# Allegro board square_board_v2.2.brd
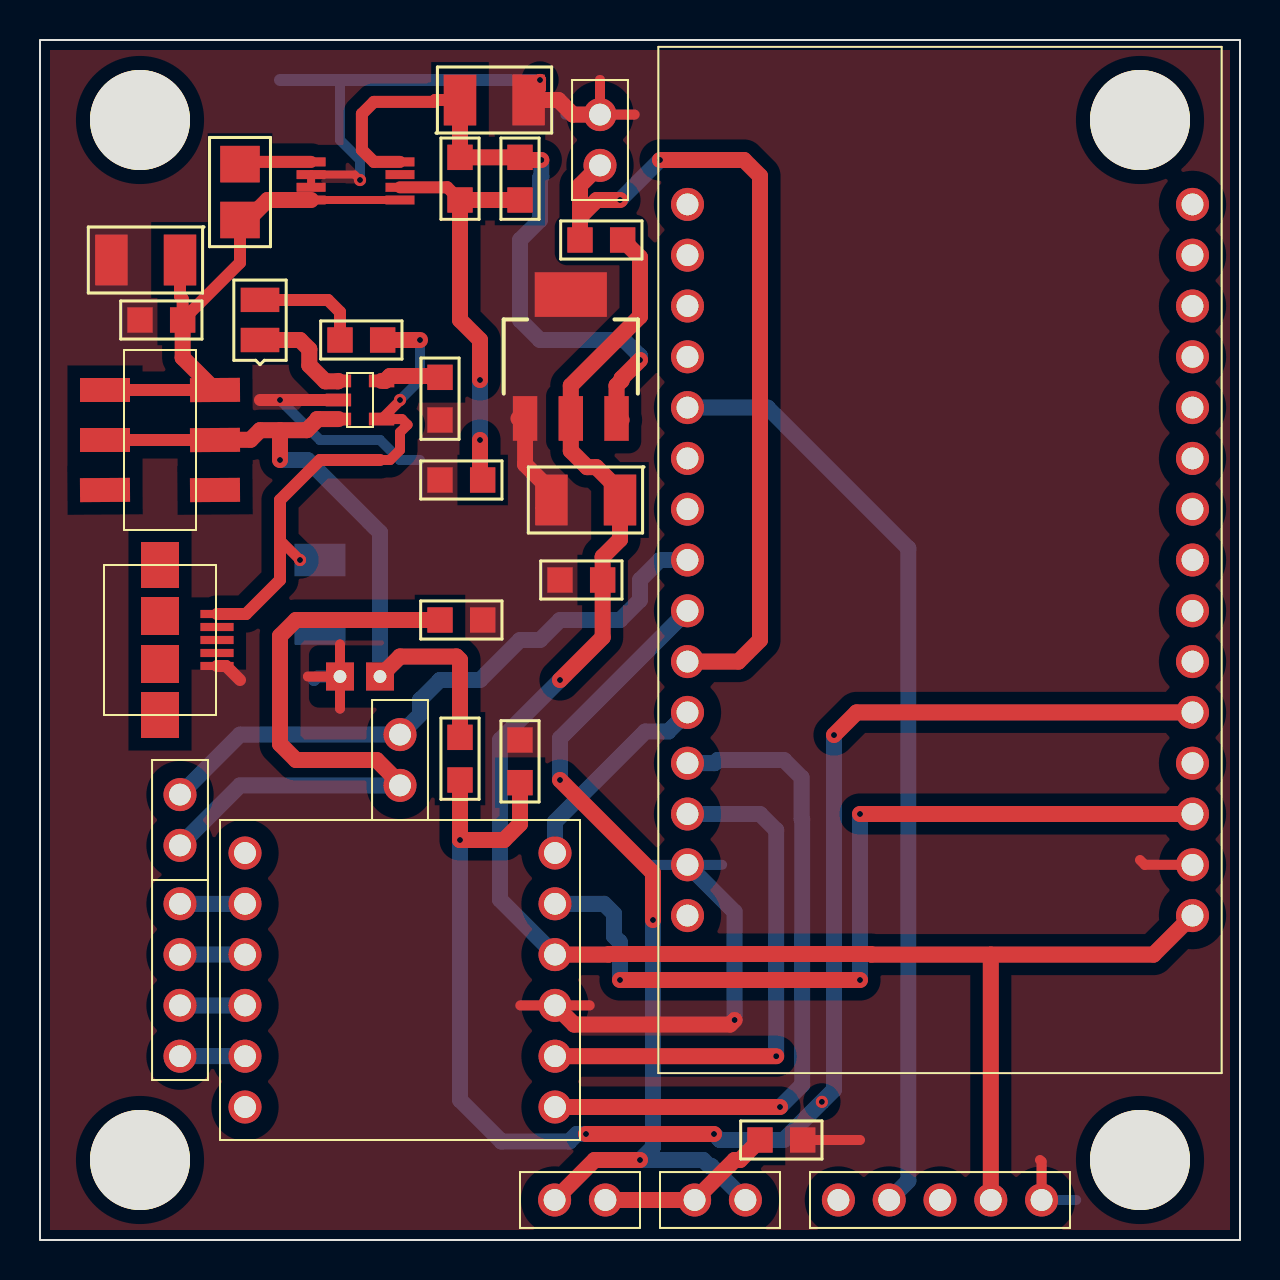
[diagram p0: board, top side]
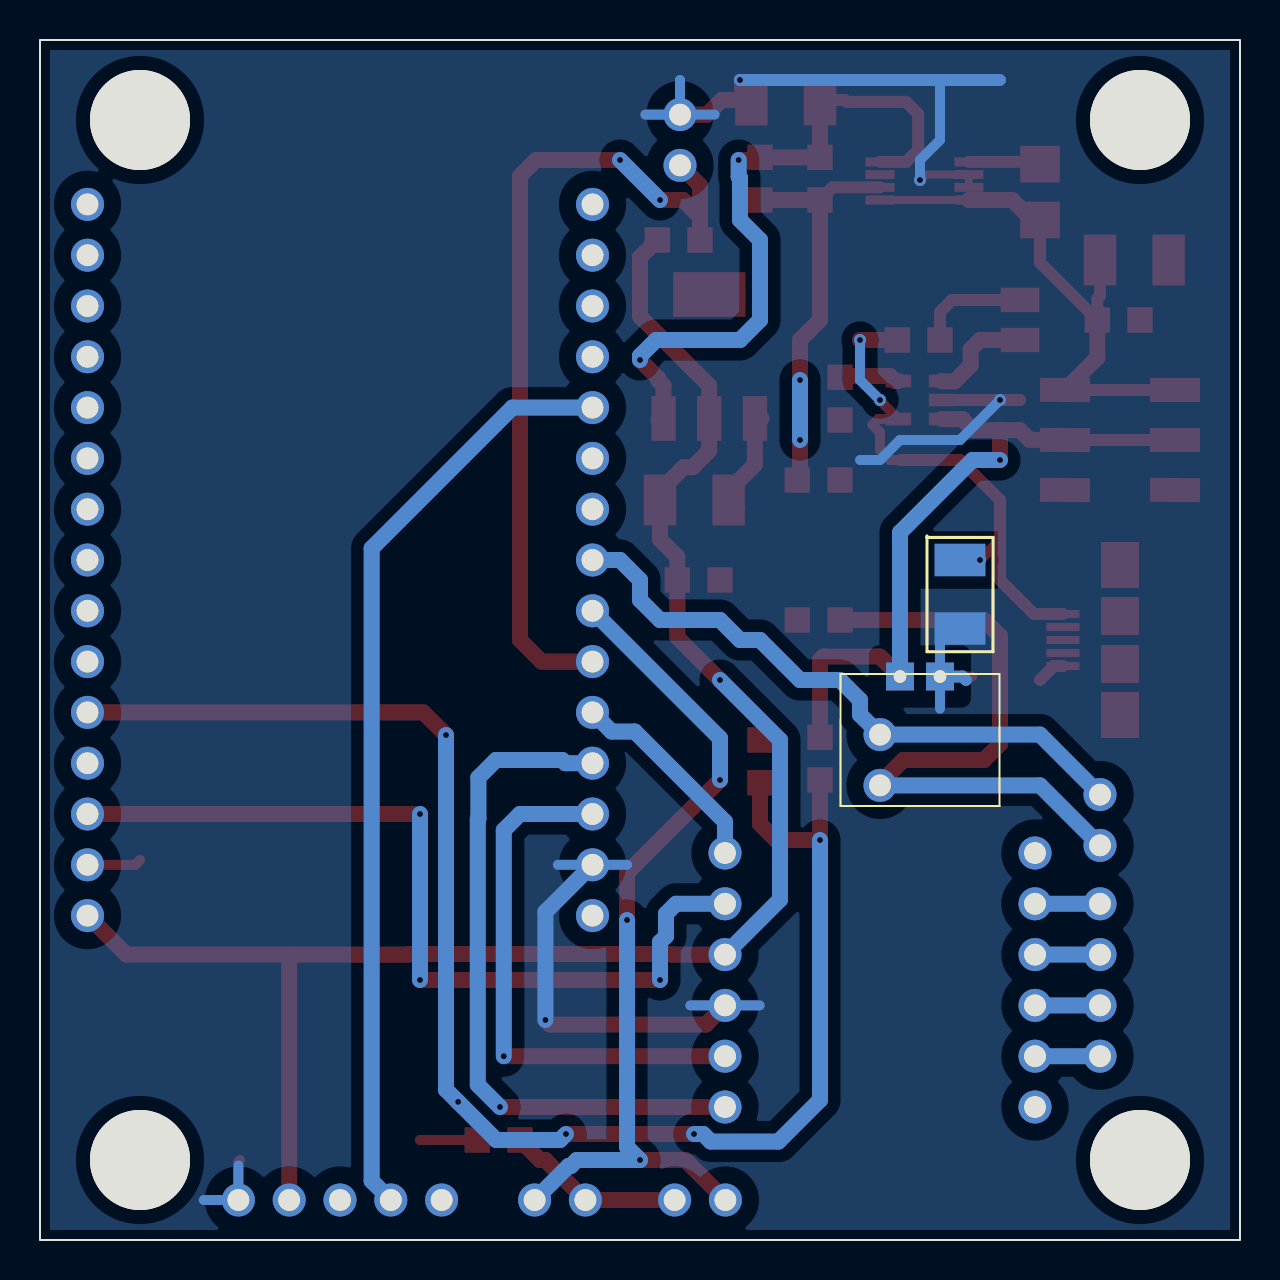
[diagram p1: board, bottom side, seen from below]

Outline 60 x 60 mm; copper layers: TOP, BOTTOM. Coordinates in mm from the lower left corner of the outline.
Outline path: rectangle 0,0 60,60

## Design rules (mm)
constraint set DEFAULT: min track width 0.5

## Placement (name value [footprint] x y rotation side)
C1  10u  [SMCT1210]  14 34 270 bottom
C2  120n  [SMC0805]  5 46 0 top
C3  10u  [SMCT1210]  7 49 180 top
C4  27p  [SMC0805]  24 52 90 top
C5  10u  [SMCT1210]  21 57 0 top
C6  120n  [SMC0805]  26 33 0 top
C7  10u  [SMCT1210]  29 37 180 top
D1  LED_RED  [SMD0805]  11 45 90 top
J1  Batterie_Lithium  [CONALIM]  16 25 0 bottom
J2  Photoresistance  [CONN2_FOOT]  28 55 0 top
J3  Micro  [CONN5_FOOT]  45 2 270 top
J4  Diode blanche1  [CONN2_FOOT]  7 21 0 top
J5  Diode rouge1  [CONN2_FOOT]  34 2 270 top
J6  Diode blanche2  [CONN2_FOOT]  18 24 0 top
J7  connDRV  [DRV_FOOT]  18 13 180 top
J8  Motors  [CONN4_FOOT]  7 13 180 top
J9  Diode rouge2  [CONN2_FOOT]  27 2 90 top
L1  4.7uH  [SML1210]  10 51 90 top
NOREF  -  [unnamed]  5 4 0 top
NOREF#2  -  [unnamed]  5 56 0 top
NOREF#3  -  [unnamed]  55 4 0 top
NOREF#4  -  [unnamed]  55 56 0 top
R1  2k  [SMR0805]  20 41 90 top
R2  470  [SMR0805]  15 45 0 top
R3  976k  [SMR0805]  21 52 90 top
R4  309k  [SMR0805]  20 38 0 top
R5  2k  [SMR0805]  21 23 90 top
R6  2k  [SMR0805]  24 25 270 top
R7  2k  [SMR0805]  27 50 0 top
R8  2k  [SMR0805]  20 31 0 top
R9  2k  [SMR0805]  36 5 0 top
SW1  Interrupteur  [INTERUPTEUR]  6 40 0 top
U1  MCP73831  [5LEADSOT23]  16 42 0 top
U2  MCP1642  [MSOP8]  18 52 90 top
U3  LD1117S33TR  [TO261AASOT223]  24 41 0 top
U4  connUSB  [CONUSB]  6 30 270 top
U5  esp32  [ESP_32]  45 34 0 top

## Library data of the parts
C1 C3 C5 C7 = CP
C2 C4 C6 = C
D1 = LED0805
J1 = CON2_0
J2 = conn2
J3 = conn5_0
J4-J6 J9 = conn2_1
J7 = connDRV
J8 = conn4
L1 = L
R1-R9 = R
SW1 = SW KEY-Y1011_0
U1 = MCP73831
U2 = MCP1642_1
U3 = LD1117S33TR_0
U4 = connUSB_1
U5 = esp32

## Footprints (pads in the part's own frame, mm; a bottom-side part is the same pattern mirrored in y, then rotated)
5LEADSOT23
  rect 1.27x0.635 smd: 1(-1.079,0.953) 2(-1.079,0) 3(-1.079,-0.953) 4(1.079,-0.953) 5(1.079,0.953)
CONALIM
  rect 1.397x1.397 hole 0.635: +(1,-3.175) -(-1,-3.175)
CONN2_FOOT
  round 1.651 hole 1.092: 1(0,1.27) 2(0,-1.27)
CONN4_FOOT
  round 1.651 hole 1.092: 1(0,3.81) 2(0,1.27) 3(0,-1.27) 4(0,-3.81)
CONN5_FOOT
  round 1.651 hole 1.092: 1(0,5.08) 2(0,2.54) 3(0,0) 4(0,-2.54) 5(0,-5.08)
CONUSB
  rect 0.406x1.651 smd: 1(-1.3,2.85) 2(-0.65,2.85) 3(0,2.85) 4(0.65,2.85) 5(1.3,2.85)
  rect 1.9x1.9 smd: 6(-1.2,0) 7(1.2,0)
  rect 2.3x1.9 smd: 8(-3.75,0) 9(3.75,0)
DRV_FOOT
  round 1.651 hole 1.092: 1(-7.75,6.35) 2(-7.75,3.81) 3(-7.75,1.27) 4(-7.75,-1.27) 5(-7.75,-3.81) 6(-7.75,-6.35) 7(7.75,-6.35) 8(7.75,-3.81) 9(7.75,-1.27) 10(7.75,1.27) 11(7.75,3.81) 12(7.75,6.35)
ESP_32
  round 1.651 hole 1.092: 1(-12.625,17.78) 2(-12.625,15.24) 3(-12.625,12.7) 4(-12.625,10.16) 5(-12.625,7.62) 6(-12.625,5.08) 7(-12.625,2.54) 8(-12.625,0) 9(-12.625,-2.54) 10(-12.625,-5.08) 11(-12.625,-7.62) 12(-12.625,-10.16) 13(-12.625,-12.7) 14(-12.625,-15.24) 15(-12.625,-17.78) 16(12.625,-17.78) 17(12.625,-15.24) 18(12.625,-12.7) 19(12.625,-10.16) 20(12.625,-7.62) 21(12.625,-5.08) 22(12.625,-2.54) 23(12.625,0) 24(12.625,2.54) 25(12.625,5.08) 26(12.625,7.62) 27(12.625,10.16) 28(12.625,12.7) 29(12.625,15.24) 30(12.625,17.78)
INTERUPTEUR
  rect 2.5x1.2 smd: 1(-2.75,2.5) 2(-2.75,0)
  rect 1.2x2.5 smd rot 90.4: 3(-2.75,-2.5) 4(2.75,2.5) 5(2.75,0) 6(2.75,-2.5)
MSOP8
  rect 0.45x1.45 smd: 1(0,0) 2(0.635,0) 3(1.27,0) 4(1.905,0) 5(1.905,4.445) 6(1.27,4.445) 7(0.635,4.445) 8(0,4.445)
SMC0805
  rect 1.27x1.27 smd: 1(0,0) 2(2.134,0)
SMCT1210
  rect 1.626x2.54 smd: 1(0,0) 2(3.429,0)
SMD0805
  rect 1.219x1.93 smd: A(2.007,0) C(0,0)
SML1210
  rect 1.829x1.981 smd: 1(0,0) 2(2.794,0)
SMR0805
  rect 1.27x1.27 smd: 1(0,0) 2(2.134,0)
TO261AASOT223
  rect 1.219x2.235 smd: 1(0,0) 2(2.54,0) 3(5.08,0)
  rect 3.607x2.235 smd: 4(2.54,6.35)
unnamed
  round 5 hole 5 unplated: (0,0)

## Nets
3.3V: C6.2 C7.1 J3.2(VDD) J7.4 R7.2 U3.2(VOUT) U5.16
5V: C4.2 C5.1 R3.2 U2.4(VOUT) U3.3
VIN: U5.15
0: C1.2 C2.1 C3.2 C5.2 C6.1 C7.2 J1.- J2.1 J3.1 J7.3 R1.1 R4.1 R6.1 R8.2 R9.2 U1.2(VSS) U2.6 U2.7 U3.1 U3.4 U4.5 U5.14 U5.17
VUSB: C1.1 R2.2 U1.4 U4.1(VCC)
N70085: J1.+ R5.2 SW1.2 SW1.5 U1.3
N70105: R1.2 U1.5
N70321: C2.2 C3.1 L1.1 SW1.1 SW1.4 U2.1 U2.8
N74007: L1.2 U2.5
N74339: C4.1 R3.1 R4.2 U2.2
N76144: J3.4 U5.5
N76694: J7.11 J8.1
N76698: J7.10 J8.2
N76711: J7.8 J8.4(OUT4)
N76717: J7.9 J8.3
N77907: J7.1 U5.12
N79860: J5.2(-) J9.2(-) R9.1
N80233: J4.2(-) J6.2(-) R8.1
N80351: J4.1 J6.1 U5.8
N80525: J5.1 J9.1 U5.9
N80737: J2.2(OUT2) R7.1 U5.10
N87816: J7.2 U5.13
N87824: J7.6 U5.11
N94189: R5.1 R6.2 U5.20
N98470: J7.5 U5.18
N700530: D1.C(CATHODE) U1.1
N701570: D1.A R2.1

Pads without a net: J3 3 5; J7 7 12; SW1 3 6; U2 3; U4 2 3 4 6 7 8 9; U5 1 2 3 4 6 7 19 21 22 23 24 25 26 27 28 29 30

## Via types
v1: diameter 0.61, hole 0.3, TOP to BOTTOM, 28 vias

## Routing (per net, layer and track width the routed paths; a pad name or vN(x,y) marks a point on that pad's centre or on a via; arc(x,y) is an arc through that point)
3.3V: length 87.4
  TOP w0.8: U5.16 55.67,14.27 47.54,14.27 ; R7.2 30,49.13 30,46.18 26.54,42.72 U3.2 26.54,39.46 27.36,38.64 27.81,38.64 29,37.46 C7.1 29,35.03 28.13,34.16 C6.2 28.13,30.13 v1(26,28) ; J3.2 47.54,14.27 ; 47.54,14.27 41.57,14.27 41.54,14.3 28.46,14.3 28.43,14.27 J7.4
  BOTTOM w0.8: v1(26,28) 23,25 23,17.02 J7.4
5V: length 35.1
  TOP w0.6: C5.1 19.76,57 19.67,56.91 16.7,56.91 16.09,56.3 16.09,54.5 16.7,53.91 U2.4
  TOP w0.8: v1(30,44) 29.08,43.08 29.08,42.97 28.83,42.72 28.83,41.25 U3.3 ; v1(25.07,54) 24.13,54 C4.2 R3.2 C5.1
  BOTTOM w0.8: v1(25.07,54) 25.07,53.17 25,53.1 25,51 24,50 24,46 25,45 29.2,45 30,44.2 v1(30,44)
0: length 104
  TOP w0.4: v1(16,53) 15.73,53.27 U2.6 U2.7
  TOP w0.5: R9.2 41,5 ; 50,4 50.08,3.92 J3.1 ; 13.39,28.18 15,28.18 ; 15,28.18 15,26.57 ; 15,28.18 15,29.78 ; 28,58 J2.1 29.73,56.27 ; 24.02,11.73 J7.3 27.48,11.73 ; U5.17 55.24,18.76 55,19
  TOP w0.6: 11,42 v1(12,42) U1.2 ; 10,28 9.3,28.7 U4.5 ; 24.25,40.75 U3.1 ; C5.2 25,57.57 v1(25,58) ; 19.73,41 R1.1 ; C7.2 25.57,37.46
  TOP w0.8: J7.3 26.71,10.77 34.5,10.77 v1(34.73,11) ; 25.16,36.59 C7.2 ; 24.25,40.75 24.25,38.77 25.57,37.46 ; J2.1 26.65,56.27 25.92,57 C5.2 ; 24.25,41.25 U3.1 23.92,41.08
  BOTTOM w0.5: 15,29.78 15,26.57 ; J2.1 28,58 ; J2.1 26.27,56.27 ; J2.1 29.73,56.27 ; 30.64,18.76 U5.14 34.11,18.76 ; 27.48,11.73 J7.3 24.02,11.73 ; v1(12,42) 14,40 17,40 18,39 19,39 ; 51.81,2 J3.1 50.08,3.73 ; v1(16,53) 16,54 15,55 15,58
  BOTTOM w0.6: v1(25,58) 12,58 ; 15,28.18 13.87,28.18 13.7,28
  BOTTOM w0.8: U5.14 34.73,16.41 v1(34.73,11)
VUSB: length 26.8
  TOP w0.5: v1(13,34) 12,35 ; 17,39 17.5,39 18,39.5 18,40.38 18.38,40.76 18.09,41.05 U1.4 18,41.97 v1(18,42)
  TOP w0.6: U4.1 10.3,31.3 12,33 12,37 14,39 17,39
  TOP w0.8: R2.2 v1(19,45)
  BOTTOM w0.5: v1(18,42) 19,43 v1(19,45) ; C1.1 v1(13,34)
N70085: length 35.7
  TOP w0.6: SW1.2 SW1.5
  TOP w0.8: 12,40.49 v1(12,39) ; 12,40.49 13.34,40.49 13.87,41.02 13.87,41.05 U1.3 ; 12,40.49 11,40.49 10.53,40.01 SW1.5 ; 17,28.18 18,29.18 20.82,29.18 21,29 R5.2
  BOTTOM w0.8: v1(12,39) 13.37,39 17,35.37 17,28.18
N70105: length 3.1
  TOP w0.8: U1.5 17.26,42.95 17.5,43.2 19.5,43.2 19.56,43.13 R1.2
N70321: length 27.5
  TOP w0.4: U2.8 U2.1
  TOP w0.6: SW1.1 SW1.4 ; L1.1 10,48.87 C2.2 7.13,47.06 7,47.2 C3.1
  TOP w0.8: SW1.4 7.13,44.12 C2.2 7,46.13 ; U2.8 11.38,52 10.38,51 L1.1
N74007: length 3.6
  TOP w0.6: L1.2 10.11,53.91 U2.5
N74339: length 20.7
  TOP w0.6: U2.2 20.37,52.64 R3.1
  TOP w0.8: v1(22,40) 22,38.13 R4.2 ; v1(22,43) 22,45 21,46 R3.1 C4.1
  BOTTOM w0.8: v1(22,43) v1(22,40)
N76144: length 46.9
  BOTTOM w0.8: U5.5 36.38,41.62 43.42,34.58 43.42,2.96 J3.4
N76694: length 3.2
  BOTTOM w0.8: J8.1 J7.11
N76698: length 3.2
  BOTTOM w0.8: J8.2 J7.10
N76711: length 3.2
  BOTTOM w0.8: J8.4 J7.8
N76717: length 3.2
  BOTTOM w0.8: J8.3 J7.9
N77907: length 34.3
  TOP w0.8: v1(37,6.65) J7.1
  BOTTOM w0.8: U5.12 33.73,23.84 33.89,24 37.2,24 38.08,23.12 38.08,21.06 38.11,21.03 38.11,7.76 v1(37,6.65)
N79860: length 9
  TOP w0.8: R9.1 35,4 34.73,4 J5.2 J9.2
N80233: length 32.9
  TOP w0.8: R8.1 12.8,31 12,30.2 12,24.8 12.8,24 16.83,24 18,22.83 J6.2
  BOTTOM w0.8: J4.2 10,22.73 J6.2
N80351: length 31.2
  BOTTOM w0.8: U5.8 31,34 30,33 30,32 29,31 26,31 25,30 24,30 22,28 20,28 19,27 19,26.27 J6.1 10,25.27 J4.1
N80525: length 43.5
  TOP w0.8: v1(30,4) 27.73,4 J9.1 ; v1(30.65,16) 30.65,18.35 v1(26,23)
  BOTTOM w0.8: J5.1 33.57,3.7 33.46,3.7 33.16,4 v1(30,4) 30.65,4.65 v1(30.65,16) ; U5.9 26,25.09 v1(26,23)
N80737: length 41.9
  TOP w0.8: 27,51.16 27.84,52 v1(29,52) ; 27,51.16 R7.1 ; 27,51.16 27,52.73 J2.2 ; U5.10 34.92,28.92 36,30 36,53.2 35.2,54 v1(31,54)
  BOTTOM w0.8: v1(31,54) v1(29,52)
N87816: length 27.1
  TOP w0.8: J7.2 v1(36.81,9.19)
  BOTTOM w0.8: U5.13 36,21.3 36.81,20.49 v1(36.81,9.19)
N87824: length 10.5
  BOTTOM w0.8: U5.11 31.42,25.42 30.26,25.42 25.75,20.91 J7.6
N94189: length 78.4
  TOP w0.8: U5.20 40.83,26.38 v1(39.7,25.25) ; R5.1 v1(21,20) 23.2,20 24,20.8 R6.2 ; v1(33.7,5.3) v1(27.3,5.3)
  BOTTOM w0.8: v1(21,20) 21,7 23.08,4.92 26.46,4.92 26.84,5.3 v1(27.3,5.3) ; v1(33.7,5.3) 34,5 37.19,5 v1(39.09,6.91) 39.7,7.51 v1(39.7,25.25)
N98470: length 43.5
  TOP w0.8: v1(41,13) v1(29,13) ; v1(41,21.3) U5.18
  BOTTOM w0.8: v1(41,13) v1(41,21.3) ; J7.5 28.2,16.81 28.7,16.31 28.7,15.19 29,14.89 v1(29,13)
N700530: length 5.3
  TOP w0.8: D1.C 13,45 13.46,44.53 13.46,43.73 14.27,42.94 14.9,42.94 U1.1
N701570: length 5.7
  TOP w0.6: R2.1 15,46.4 14.4,47 11.01,47 D1.A

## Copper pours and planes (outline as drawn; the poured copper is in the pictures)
0 on TOP, BOTTOM: 0.5,59.5 59.5,59.5 59.5,0.5 0.5,0.5
